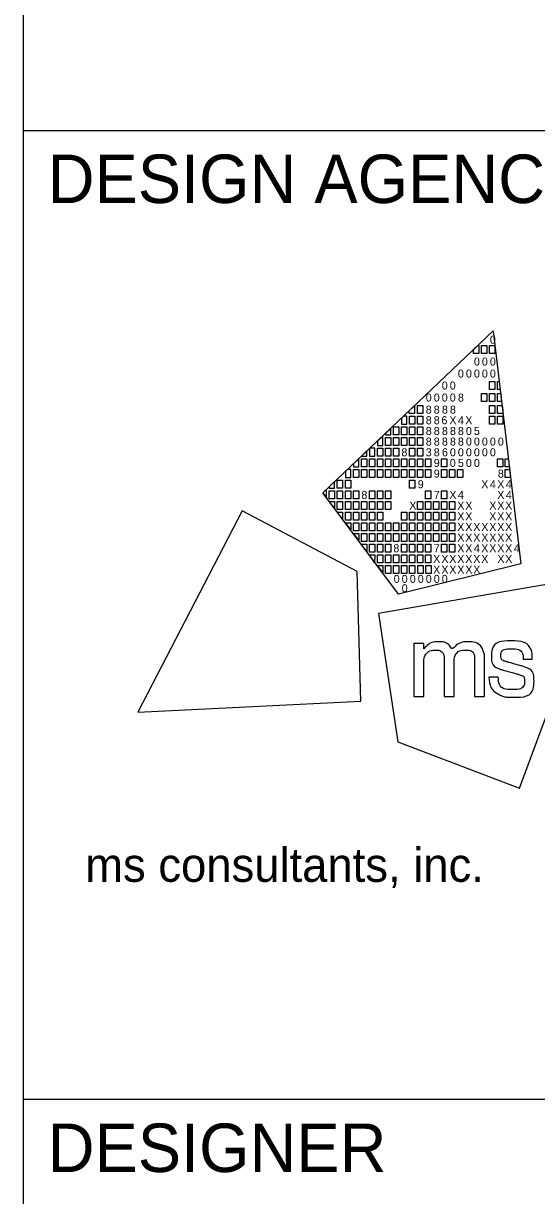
# Model space of a CAD drawing. Extents: x -0.1 to 34, y 0 to 22.
# Drawn here: x 32 to 33.058, y 2.301 to 4.721 of the extents above; entities that cross this region are included whole.
import ezdxf

# ---------------------------------------------------------------- set-up
doc = ezdxf.new("R2010")
doc.units = 0
doc.layers.add('SH_Border', color=7, linetype='Continuous')
doc.layers.add('SH_Data', color=7, linetype='Continuous')

msp = doc.modelspace()

# ---------------------------------------------------------------- linework, layer by layer
at = {"layer": 'SH_Border'}
for p, q in [((32, 0.5), (32, 21.5)), ((32, 4.5), (33.5, 4.5)), ((32, 2.5), (33.5, 2.5))]:
    msp.add_line(p, q, dxfattribs=at)
at = {"layer": 'SH_Data'}
for p, q in [((32.6175, 3.7519), (32.9688, 4.0861)), ((32.9688, 4.0861), (32.9688, 4.0861)), ((32.9688, 4.0861), (33.0253, 3.6052)), ((32.773, 3.543), (32.6175, 3.7519)), ((33.0253, 3.6052), (32.773, 3.543)), ((32.75, 3.5), (32.75, 3.5))]:
    msp.add_line(p, q, dxfattribs=at)
for points in [[(32.9279, 4.0472), (32.9369, 4.0558), (32.9389, 4.0558), (32.9389, 4.0393), (32.9279, 4.0393)], [(32.9444, 4.0558), (32.9554, 4.0558), (32.9554, 4.0393), (32.9444, 4.0393)], [(32.9609, 4.0558), (32.9719, 4.0558), (32.9719, 4.0393), (32.9609, 4.0393)], [(32.9606, 3.9815), (32.9716, 3.9815), (32.9716, 3.965), (32.9606, 3.965)], [(32.9771, 3.9815), (32.9811, 3.9815), (32.983, 3.965), (32.9771, 3.965)], [(32.9441, 3.9567), (32.9551, 3.9567), (32.9551, 3.9402), (32.9441, 3.9402)], [(32.9606, 3.9567), (32.9716, 3.9567), (32.9716, 3.9402), (32.9606, 3.9402)], [(32.9771, 3.9567), (32.984, 3.9567), (32.9859, 3.9402), (32.9771, 3.9402)], [(32.7953, 3.9211), (32.8064, 3.9316), (32.8064, 3.9154), (32.7953, 3.9154)], [(32.8123, 3.9319), (32.8233, 3.9319), (32.8233, 3.9154), (32.8123, 3.9154)], [(32.9606, 3.9319), (32.9716, 3.9319), (32.9716, 3.9154), (32.9606, 3.9154)], [(32.9771, 3.9319), (32.9869, 3.9319), (32.9881, 3.9218), (32.9881, 3.9154), (32.9771, 3.9154)], [(32.7958, 3.9099), (32.8068, 3.9099), (32.8068, 3.8934), (32.7958, 3.8934)], [(32.8123, 3.9099), (32.8233, 3.9099), (32.8233, 3.8934), (32.8123, 3.8934)], [(32.9606, 3.9099), (32.9716, 3.9099), (32.9716, 3.8934), (32.9606, 3.8934)], [(32.9771, 3.9099), (32.9881, 3.9099), (32.9881, 3.8934), (32.9771, 3.8934)], [(32.7627, 3.8879), (32.7737, 3.8879), (32.7737, 3.8714), (32.7627, 3.8714)], [(32.7793, 3.8879), (32.7903, 3.8879), (32.7903, 3.8714), (32.7793, 3.8714)], [(32.7958, 3.8879), (32.8068, 3.8879), (32.8068, 3.8714), (32.7958, 3.8714)], [(32.8123, 3.8879), (32.8233, 3.8879), (32.8233, 3.8714), (32.8123, 3.8714)], [(32.7462, 3.8659), (32.7572, 3.8659), (32.7572, 3.8494), (32.7462, 3.8494)], [(32.7627, 3.8659), (32.7737, 3.8659), (32.7737, 3.8494), (32.7627, 3.8494)], [(32.7793, 3.8659), (32.7903, 3.8659), (32.7903, 3.8494), (32.7793, 3.8494)], [(32.7958, 3.8659), (32.8068, 3.8659), (32.8068, 3.8494), (32.7958, 3.8494)], [(32.8123, 3.8659), (32.8233, 3.8659), (32.8233, 3.8494), (32.8123, 3.8494)], [(32.7297, 3.8439), (32.7407, 3.8439), (32.7407, 3.8273), (32.7297, 3.8273)], [(32.7462, 3.8439), (32.7572, 3.8439), (32.7572, 3.8273), (32.7462, 3.8273)], [(32.7627, 3.8439), (32.7737, 3.8439), (32.7737, 3.8273), (32.7627, 3.8273)], [(32.7958, 3.8439), (32.8068, 3.8439), (32.8068, 3.8273), (32.7958, 3.8273)], [(32.8123, 3.8439), (32.8233, 3.8439), (32.8233, 3.8273), (32.8123, 3.8273)], [(32.6802, 3.7998), (32.6912, 3.7998), (32.6912, 3.7833), (32.6802, 3.7833)], [(32.6967, 3.8218), (32.7077, 3.8218), (32.7077, 3.8053), (32.6967, 3.8053)], [(32.6967, 3.7998), (32.7077, 3.7998), (32.7077, 3.7833), (32.6967, 3.7833)], [(32.7132, 3.8218), (32.7242, 3.8218), (32.7242, 3.8053), (32.7132, 3.8053)], [(32.7132, 3.7998), (32.7242, 3.7998), (32.7242, 3.7833), (32.7132, 3.7833)], [(32.7297, 3.8218), (32.7407, 3.8218), (32.7407, 3.8053), (32.7297, 3.8053)], [(32.7297, 3.7998), (32.7407, 3.7998), (32.7407, 3.7833), (32.7297, 3.7833)], [(32.7462, 3.8218), (32.7572, 3.8218), (32.7572, 3.8053), (32.7462, 3.8053)], [(32.7462, 3.7998), (32.7572, 3.7998), (32.7572, 3.7833), (32.7462, 3.7833)], [(32.7627, 3.8218), (32.7737, 3.8218), (32.7737, 3.8053), (32.7627, 3.8053)], [(32.7627, 3.7998), (32.7737, 3.7998), (32.7737, 3.7833), (32.7627, 3.7833)], [(32.7793, 3.8218), (32.7903, 3.8218), (32.7903, 3.8053), (32.7793, 3.8053)], [(32.7793, 3.7998), (32.7903, 3.7998), (32.7903, 3.7833), (32.7793, 3.7833)], [(32.7958, 3.8218), (32.8068, 3.8218), (32.8068, 3.8053), (32.7958, 3.8053)], [(32.7958, 3.7998), (32.8068, 3.7998), (32.8068, 3.7833), (32.7958, 3.7833)], [(32.8123, 3.8218), (32.8233, 3.8218), (32.8233, 3.8053), (32.8123, 3.8053)], [(32.8123, 3.7998), (32.8233, 3.7998), (32.8233, 3.7833), (32.8123, 3.7833)], [(32.8288, 3.8218), (32.8398, 3.8218), (32.8398, 3.8053), (32.8288, 3.8053)], [(32.8288, 3.7998), (32.8398, 3.7998), (32.8398, 3.7833), (32.8288, 3.7833)], [(32.8618, 3.8218), (32.8728, 3.8218), (32.8728, 3.8053), (32.8618, 3.8053)], [(32.8618, 3.7998), (32.8728, 3.7998), (32.8728, 3.7833), (32.8618, 3.7833)], [(32.8783, 3.7998), (32.8893, 3.7998), (32.8893, 3.7833), (32.8783, 3.7833)], [(32.8947, 3.7998), (32.9057, 3.7998), (32.9057, 3.7833), (32.8947, 3.7833)], [(32.9771, 3.8218), (32.9881, 3.8218), (32.9881, 3.8053), (32.9771, 3.8053)], [(32.9935, 3.8218), (32.9998, 3.8218), (33.0018, 3.8053), (32.9935, 3.8053)], [(32.9935, 3.7998), (33.0024, 3.7998), (33.0044, 3.7833), (32.9935, 3.7833)], [(32.6471, 3.7778), (32.6581, 3.7778), (32.6581, 3.7613), (32.6471, 3.7613)], [(32.6637, 3.7778), (32.6747, 3.7778), (32.6747, 3.7613), (32.6637, 3.7613)], [(32.7958, 3.7778), (32.8068, 3.7778), (32.8068, 3.7613), (32.7958, 3.7613)], [(32.6306, 3.7558), (32.6416, 3.7558), (32.6416, 3.7393), (32.6306, 3.7393)], [(32.6471, 3.7558), (32.6581, 3.7558), (32.6581, 3.7393), (32.6471, 3.7393)], [(32.6637, 3.7558), (32.6747, 3.7558), (32.6747, 3.7393), (32.6637, 3.7393)], [(32.6802, 3.7558), (32.6912, 3.7558), (32.6912, 3.7393), (32.6802, 3.7393)], [(32.7132, 3.7558), (32.7242, 3.7558), (32.7242, 3.7393), (32.7132, 3.7393)], [(32.7297, 3.7558), (32.7407, 3.7558), (32.7407, 3.7393), (32.7297, 3.7393)], [(32.7462, 3.7558), (32.7572, 3.7558), (32.7572, 3.7393), (32.7462, 3.7393)], [(32.8288, 3.7558), (32.8398, 3.7558), (32.8398, 3.7393), (32.8288, 3.7393)], [(32.8618, 3.7558), (32.8728, 3.7558), (32.8728, 3.7393), (32.8618, 3.7393)], [(32.6306, 3.7338), (32.6416, 3.7338), (32.6416, 3.72)], [(32.6471, 3.7338), (32.6581, 3.7338), (32.6581, 3.7173), (32.6471, 3.7173)], [(32.6637, 3.7338), (32.6747, 3.7338), (32.6747, 3.7173), (32.6637, 3.7173)], [(32.6802, 3.7338), (32.6912, 3.7338), (32.6912, 3.7173), (32.6802, 3.7173)], [(32.6967, 3.7338), (32.7077, 3.7338), (32.7077, 3.7173), (32.6967, 3.7173)], [(32.7132, 3.7338), (32.7242, 3.7338), (32.7242, 3.7173), (32.7132, 3.7173)], [(32.7297, 3.7338), (32.7407, 3.7338), (32.7407, 3.7173), (32.7297, 3.7173)], [(32.7462, 3.7338), (32.7572, 3.7338), (32.7572, 3.7173), (32.7462, 3.7173)], [(32.8123, 3.7338), (32.8233, 3.7338), (32.8233, 3.7173), (32.8123, 3.7173)], [(32.8288, 3.7338), (32.8398, 3.7338), (32.8398, 3.7173), (32.8288, 3.7173)], [(32.8453, 3.7338), (32.8563, 3.7338), (32.8563, 3.7173), (32.8453, 3.7173)], [(32.8618, 3.7338), (32.8728, 3.7338), (32.8728, 3.7173), (32.8618, 3.7173)], [(32.8783, 3.7338), (32.8893, 3.7338), (32.8893, 3.7173), (32.8783, 3.7173)], [(32.6471, 3.7117), (32.6581, 3.7117), (32.6581, 3.698)], [(32.6637, 3.7117), (32.6747, 3.7117), (32.6747, 3.6952), (32.6637, 3.6952)], [(32.6802, 3.7117), (32.6912, 3.7117), (32.6912, 3.6952), (32.6802, 3.6952)], [(32.6967, 3.7117), (32.7077, 3.7117), (32.7077, 3.6952), (32.6967, 3.6952)], [(32.7132, 3.7117), (32.7242, 3.7117), (32.7242, 3.6952), (32.7132, 3.6952)], [(32.7297, 3.7117), (32.7407, 3.7117), (32.7407, 3.6952), (32.7297, 3.6952)], [(32.7793, 3.7117), (32.7903, 3.7117), (32.7903, 3.6952), (32.7793, 3.6952)], [(32.7958, 3.7117), (32.8068, 3.7117), (32.8068, 3.6952), (32.7958, 3.6952)], [(32.8123, 3.7117), (32.8233, 3.7117), (32.8233, 3.6952), (32.8123, 3.6952)], [(32.8288, 3.7117), (32.8398, 3.7117), (32.8398, 3.6952), (32.8288, 3.6952)], [(32.8453, 3.7117), (32.8563, 3.7117), (32.8563, 3.6952), (32.8453, 3.6952)], [(32.8618, 3.7117), (32.8728, 3.7117), (32.8728, 3.6952), (32.8618, 3.6952)], [(32.8783, 3.7117), (32.8893, 3.7117), (32.8893, 3.6952), (32.8783, 3.6952)], [(32.6637, 3.6897), (32.6747, 3.6897), (32.6747, 3.676)], [(32.6747, 3.6897), (32.6747, 3.6897), (32.6747, 3.6897)], [(32.6802, 3.6897), (32.6912, 3.6897), (32.6912, 3.6732), (32.6802, 3.6732)], [(32.6967, 3.6897), (32.7077, 3.6897), (32.7077, 3.6732), (32.6967, 3.6732)], [(32.7132, 3.6897), (32.7242, 3.6897), (32.7242, 3.6732), (32.7132, 3.6732)], [(32.7297, 3.6897), (32.7407, 3.6897), (32.7407, 3.6732), (32.7297, 3.6732)], [(32.7462, 3.6897), (32.7572, 3.6897), (32.7572, 3.6732), (32.7462, 3.6732)], [(32.7627, 3.6897), (32.7737, 3.6897), (32.7737, 3.6732), (32.7627, 3.6732)], [(32.7793, 3.6897), (32.7903, 3.6897), (32.7903, 3.6732), (32.7793, 3.6732)], [(32.7958, 3.6897), (32.8068, 3.6897), (32.8068, 3.6732), (32.7958, 3.6732)], [(32.8123, 3.6897), (32.8233, 3.6897), (32.8233, 3.6732), (32.8123, 3.6732)], [(32.8288, 3.6897), (32.8398, 3.6897), (32.8398, 3.6732), (32.8288, 3.6732)], [(32.8453, 3.6897), (32.8563, 3.6897), (32.8563, 3.6732), (32.8453, 3.6732)], [(32.8618, 3.6897), (32.8728, 3.6897), (32.8728, 3.6732), (32.8618, 3.6732)], [(32.8783, 3.6897), (32.8893, 3.6897), (32.8893, 3.6732), (32.8783, 3.6732)], [(32.6802, 3.6677), (32.6912, 3.6677), (32.6912, 3.654)], [(32.6967, 3.6677), (32.7077, 3.6677), (32.7077, 3.6512), (32.6967, 3.6512)], [(32.7132, 3.6677), (32.7242, 3.6677), (32.7242, 3.6512), (32.7132, 3.6512)], [(32.7297, 3.6677), (32.7407, 3.6677), (32.7407, 3.6512), (32.7297, 3.6512)], [(32.7462, 3.6677), (32.7572, 3.6677), (32.7572, 3.6512), (32.7462, 3.6512)], [(32.7627, 3.6677), (32.7737, 3.6677), (32.7737, 3.6512), (32.7627, 3.6512)], [(32.7793, 3.6677), (32.7903, 3.6677), (32.7903, 3.6512), (32.7793, 3.6512)], [(32.7958, 3.6677), (32.8068, 3.6677), (32.8068, 3.6512), (32.7958, 3.6512)], [(32.8123, 3.6677), (32.8233, 3.6677), (32.8233, 3.6512), (32.8123, 3.6512)], [(32.8288, 3.6677), (32.8398, 3.6677), (32.8398, 3.6512), (32.8288, 3.6512)], [(32.8453, 3.6677), (32.8563, 3.6677), (32.8563, 3.6512), (32.8453, 3.6512)], [(32.8618, 3.6677), (32.8728, 3.6677), (32.8728, 3.6512), (32.8618, 3.6512)], [(32.8783, 3.6677), (32.8893, 3.6677), (32.8893, 3.6512), (32.8783, 3.6512)], [(32.7077, 3.6305), (32.6965, 3.6457), (32.7077, 3.6457)], [(32.7132, 3.6457), (32.7242, 3.6457), (32.7242, 3.6292), (32.7132, 3.6292)], [(32.7297, 3.6457), (32.7407, 3.6457), (32.7407, 3.6292), (32.7297, 3.6292)], [(32.7462, 3.6457), (32.7572, 3.6457), (32.7572, 3.6292), (32.7462, 3.6292)], [(32.7793, 3.6457), (32.7903, 3.6457), (32.7903, 3.6292), (32.7793, 3.6292)], [(32.7958, 3.6457), (32.8068, 3.6457), (32.8068, 3.6292), (32.7958, 3.6292)], [(32.8123, 3.6457), (32.8233, 3.6457), (32.8233, 3.6292), (32.8123, 3.6292)], [(32.8288, 3.6457), (32.8398, 3.6457), (32.8398, 3.6292), (32.8288, 3.6292)], [(32.8618, 3.6457), (32.8728, 3.6457), (32.8728, 3.6292), (32.8618, 3.6292)], [(32.8783, 3.6457), (32.8893, 3.6457), (32.8893, 3.6292), (32.8783, 3.6292)], [(32.724, 3.6082), (32.7132, 3.6237), (32.7242, 3.6237)], [(32.7297, 3.6237), (32.7407, 3.6237), (32.7407, 3.6072), (32.7297, 3.6072)], [(32.7462, 3.6237), (32.7572, 3.6237), (32.7572, 3.6072), (32.7462, 3.6072)], [(32.7627, 3.6237), (32.7737, 3.6237), (32.7737, 3.6072), (32.7627, 3.6072)], [(32.7793, 3.6237), (32.7903, 3.6237), (32.7903, 3.6072), (32.7793, 3.6072)], [(32.7958, 3.6237), (32.8068, 3.6237), (32.8068, 3.6072), (32.7958, 3.6072)], [(32.8123, 3.6237), (32.8233, 3.6237), (32.8233, 3.6072), (32.8123, 3.6072)], [(32.8288, 3.6237), (32.8398, 3.6237), (32.8398, 3.6072), (32.8288, 3.6072)], [(32.7302, 3.6017), (32.7407, 3.6017), (32.7408, 3.5875)], [(32.7463, 3.6017), (32.7573, 3.6017), (32.7573, 3.5852), (32.7463, 3.5852)], [(32.763, 3.6017), (32.774, 3.6017), (32.774, 3.5852), (32.763, 3.5852)], [(32.7794, 3.6017), (32.7904, 3.6017), (32.7904, 3.5852), (32.7794, 3.5852)], [(32.796, 3.6017), (32.807, 3.6017), (32.807, 3.5852), (32.796, 3.5852)], [(32.8129, 3.6017), (32.8239, 3.6017), (32.8239, 3.5851), (32.8129, 3.5851)], [(32.8296, 3.6017), (32.8406, 3.6017), (32.8406, 3.5851), (32.8296, 3.5851)]]:
    msp.add_lwpolyline(points, close=True, dxfattribs=at)
for points in [[(32.7903, 3.9099), (32.7836, 3.9099), (32.7793, 3.9058), (32.7793, 3.8934), (32.7903, 3.8934), (32.7903, 3.9099)], [(32.7572, 3.8849), (32.7462, 3.8744), (32.7462, 3.8714), (32.7572, 3.8714), (32.7572, 3.8849)], [(32.7407, 3.8691), (32.7297, 3.8587), (32.7297, 3.8494), (32.7407, 3.8494), (32.7407, 3.8691)], [(32.7077, 3.8377), (32.6968, 3.8273), (32.7077, 3.8273), (32.7077, 3.8377)], [(32.7242, 3.8439), (32.7141, 3.8439), (32.7132, 3.843), (32.7132, 3.8273), (32.7242, 3.8273), (32.7242, 3.8439)], [(32.6747, 3.7998), (32.6679, 3.7998), (32.6637, 3.7958), (32.6637, 3.7833), (32.6747, 3.7833), (32.6747, 3.7998)], [(32.6912, 3.822), (32.6802, 3.8115), (32.6802, 3.8053), (32.6912, 3.8053), (32.6912, 3.822)], [(32.6416, 3.7749), (32.6306, 3.7644), (32.6306, 3.7613), (32.6416, 3.7613), (32.6416, 3.7749)], [(32.6251, 3.7558), (32.6216, 3.7558), (32.6175, 3.7519), (32.6251, 3.7417), (32.6251, 3.7558)], [(32.4512, 3.7149), (32.2359, 3.2988), (32.6956, 3.3215), (32.6884, 3.5892), (32.4512, 3.7149)], [(33.0229, 3.1422), (33.1859, 3.5814), (32.7324, 3.5029), (32.7722, 3.2381), (33.0229, 3.1422)]]:
    msp.add_lwpolyline(points, dxfattribs=at)
for points in [[(32.8048, 3.3315), (32.8048, 3.3315), (32.8048, 3.4409), (32.8048, 3.4409), (32.8048, 3.4409), (32.8255, 3.4409), (32.8255, 3.4409), (32.8255, 3.4409), (32.8255, 3.4297), (32.8255, 3.4297), (32.8346, 3.4399), (32.8457, 3.4445), (32.8555, 3.4445), (32.8688, 3.4445), (32.8791, 3.4372), (32.8837, 3.4266), (32.8915, 3.4381), (32.905, 3.4446), (32.9166, 3.4446), (32.9325, 3.4446), (32.9451, 3.435), (32.9494, 3.4213), (32.9494, 3.4212), (32.9494, 3.4212), (32.9494, 3.4212), (32.9501, 3.419), (32.9506, 3.4172), (32.9506, 3.4071), (32.9506, 3.4071), (32.9506, 3.3314), (32.9506, 3.3314), (32.9506, 3.3314), (32.9303, 3.3314), (32.9303, 3.3314), (32.9303, 3.3314), (32.9303, 3.4048), (32.9303, 3.4048), (32.9303, 3.4201), (32.9219, 3.4274), (32.911, 3.4274), (32.8995, 3.4274), (32.8879, 3.4171), (32.8879, 3.4001), (32.8879, 3.4001), (32.8879, 3.3315), (32.8879, 3.3315), (32.8879, 3.3315), (32.8674, 3.3315), (32.8674, 3.3315), (32.8674, 3.3315), (32.8674, 3.4059), (32.8674, 3.4059), (32.8674, 3.4203), (32.8588, 3.4274), (32.8496, 3.4274), (32.8384, 3.4274), (32.8254, 3.417), (32.8254, 3.3962), (32.8254, 3.3962), (32.8254, 3.3315), (32.8254, 3.3315), (32.8254, 3.3315), (32.8048, 3.3315), (32.8048, 3.3315)], [(32.9595, 3.3709), (32.9595, 3.3709), (32.9595, 3.3717), (32.9595, 3.3717), (32.9595, 3.3717), (32.9603, 3.3717), (32.9603, 3.3717), (32.9603, 3.3717), (32.9783, 3.3717), (32.9783, 3.3717), (32.9783, 3.3717), (32.9789, 3.3717), (32.9789, 3.3717), (32.9789, 3.3717), (32.979, 3.371), (32.979, 3.371), (32.9803, 3.3554), (32.9887, 3.346), (33.009, 3.346), (33.0273, 3.346), (33.0333, 3.3554), (33.0333, 3.3631), (33.0333, 3.3732), (33.0256, 3.3758), (33.0175, 3.378), (33.0175, 3.378), (32.987, 3.3867), (32.987, 3.3867), (32.972, 3.3909), (32.9648, 3.4019), (32.9648, 3.4142), (32.9648, 3.4303), (32.9768, 3.4462), (33.0052, 3.4462), (33.0348, 3.4462), (33.0489, 3.4285), (33.0489, 3.4095), (33.0489, 3.4095), (33.0489, 3.4087), (33.0489, 3.4087), (33.0489, 3.4087), (33.0482, 3.4087), (33.0482, 3.4087), (33.0482, 3.4087), (33.0312, 3.4087), (33.0312, 3.4087), (33.0312, 3.4087), (33.0305, 3.4087), (33.0305, 3.4087), (33.0305, 3.4087), (33.0305, 3.4094), (33.0305, 3.4094), (33.0301, 3.4208), (33.0226, 3.43), (33.0056, 3.43), (32.9891, 3.43), (32.9843, 3.4218), (32.9843, 3.4157), (32.9843, 3.4108), (32.9869, 3.4059), (32.9959, 3.4033), (32.9959, 3.4033), (33.0255, 3.3948), (33.0255, 3.3948), (33.0462, 3.3889), (33.0527, 3.3777), (33.0527, 3.3639), (33.0527, 3.3462), (33.041, 3.3298), (33.0087, 3.3298), (32.9952, 3.3298), (32.9877, 3.3321), (32.9823, 3.3348), (32.969, 3.3414), (32.9609, 3.3536), (32.9595, 3.3709)]]:
    msp.add_open_spline(points, degree=3, dxfattribs=at)

# ---------------------------------------------------------------- texts
for s, p in [('DESIGN AGENCY', (32.05, 4.35)), ('DESIGNER', (32.05, 2.35))]:
    msp.add_text(s, height=0.1, dxfattribs=at).set_placement(p)
for s, height, p in [('0', 0.0165, (32.9617, 4.0597)), ('0', 0.0165, (32.9288, 4.0145)), ('0', 0.0165, (32.9452, 4.0145)), ('0', 0.0165, (32.9617, 4.0145)), ('0', 0.0165, (32.8958, 3.9897)), ('0', 0.0165, (32.9123, 3.9897)), ('0', 0.0165, (32.9288, 3.9897)), ('0', 0.0165, (32.9452, 3.9897)), ('0', 0.0165, (32.9617, 3.9897)), ('0', 0.0165, (32.8625, 3.965)), ('0', 0.0165, (32.879, 3.965)), ('0', 0.0165, (32.8295, 3.9402)), ('0', 0.0165, (32.846, 3.9402)), ('0', 0.0165, (32.8625, 3.9402)), ('0', 0.0165, (32.879, 3.9402)), ('8', 0.0165, (32.8958, 3.9402)), ('8', 0.0165, (32.8295, 3.9154)), ('8', 0.0165, (32.846, 3.9154)), ('8', 0.0165, (32.8628, 3.9154)), ('8', 0.0165, (32.8793, 3.9154)), ('8', 0.0165, (32.8295, 3.8934)), ('8', 0.0165, (32.846, 3.8934)), ('6', 0.0165, (32.8618, 3.8934)), ('X', 0.0165, (32.8781, 3.8934)), ('4', 0.0165, (32.8958, 3.8934)), ('X', 0.0165, (32.911, 3.8934)), ('8', 0.0165, (32.8295, 3.8713)), ('8', 0.0165, (32.846, 3.8713)), ('8', 0.0165, (32.8628, 3.8713)), ('8', 0.0165, (32.8794, 3.8713)), ('8', 0.0165, (32.8958, 3.8713)), ('0', 0.0165, (32.9123, 3.8713)), ('5', 0.0165, (32.9287, 3.8713)), ('8', 0.0165, (32.8295, 3.8494)), ('8', 0.0165, (32.846, 3.8494)), ('8', 0.0165, (32.8628, 3.8494)), ('8', 0.0165, (32.8794, 3.8494)), ('8', 0.0165, (32.8958, 3.8494)), ('0', 0.0165, (32.9123, 3.8494)), ('0', 0.0165, (32.9288, 3.8494)), ('0', 0.0165, (32.9452, 3.8494)), ('0', 0.0165, (32.9617, 3.8494)), ('0', 0.0165, (32.9782, 3.8494)), ('8', 0.0165, (32.7793, 3.8273)), ('3', 0.0165, (32.8295, 3.8273)), ('8', 0.0165, (32.846, 3.8273)), ('6', 0.0165, (32.8629, 3.8273)), ('0', 0.0165, (32.8793, 3.8273)), ('0', 0.0165, (32.8958, 3.8273)), ('0', 0.0165, (32.9123, 3.8273)), ('0', 0.0165, (32.9288, 3.8273)), ('0', 0.0165, (32.9452, 3.8273)), ('0', 0.0165, (32.9617, 3.8273)), ('9', 0.0165, (32.846, 3.8053)), ('9', 0.0165, (32.846, 3.7833)), ('0', 0.0165, (32.879, 3.8053)), ('5', 0.0165, (32.8957, 3.8053)), ('0', 0.0165, (32.9123, 3.8053)), ('0', 0.0165, (32.9288, 3.8053)), ('8', 0.0165, (32.9781, 3.7833)), ('9', 0.0165, (32.813, 3.7613)), ('X', 0.0165, (32.9439, 3.7613)), ('4', 0.0165, (32.9617, 3.7613)), ('X', 0.0165, (32.9769, 3.7613)), ('4', 0.0165, (32.9946, 3.7613)), ('8', 0.0165, (32.6967, 3.7393)), ('7', 0.0165, (32.846, 3.7393)), ('X', 0.0165, (32.8781, 3.7393)), ('4', 0.0165, (32.8958, 3.7393)), ('X', 0.0165, (32.9769, 3.7393)), ('4', 0.0165, (32.9946, 3.7393)), ('X', 0.0165, (32.7955, 3.7173)), ('X', 0.0165, (32.8945, 3.7173)), ('X', 0.0165, (32.911, 3.7173)), ('X', 0.0165, (32.9604, 3.7173)), ('X', 0.0165, (32.9769, 3.7173)), ('X', 0.0165, (32.9933, 3.7173)), ('X', 0.0165, (32.8945, 3.6952)), ('X', 0.0165, (32.911, 3.6952)), ('X', 0.0165, (32.9604, 3.6952)), ('X', 0.0165, (32.9769, 3.6952)), ('X', 0.0165, (32.9933, 3.6952)), ('X', 0.0165, (32.8945, 3.6732)), ('X', 0.0165, (32.911, 3.6732)), ('X', 0.0165, (32.9274, 3.6732)), ('X', 0.0165, (32.9439, 3.6732)), ('X', 0.0165, (32.9604, 3.6732)), ('X', 0.0165, (32.9769, 3.6732)), ('X', 0.0165, (32.9933, 3.6732)), ('X', 0.0165, (32.8945, 3.6512)), ('X', 0.0165, (32.911, 3.6512)), ('X', 0.0165, (32.9274, 3.6512)), ('X', 0.0165, (32.9439, 3.6512)), ('X', 0.0165, (32.9604, 3.6512)), ('X', 0.0165, (32.9769, 3.6512)), ('X', 0.0165, (32.9933, 3.6512)), ('8', 0.0165, (32.7627, 3.6292)), ('7', 0.0165, (32.846, 3.6292)), ('X', 0.0165, (32.8945, 3.6292)), ('X', 0.0165, (32.911, 3.6292)), ('4', 0.0165, (32.9288, 3.6292)), ('X', 0.0165, (32.9439, 3.6292)), ('X', 0.0165, (32.9604, 3.6292)), ('X', 0.0165, (32.9769, 3.6292)), ('X', 0.0165, (32.9933, 3.6292)), ('4', 0.0165, (33.0111, 3.6292)), ('X', 0.0165, (32.8447, 3.6072)), ('X', 0.0165, (32.8616, 3.6072)), ('X', 0.0165, (32.878, 3.6072)), ('X', 0.0165, (32.8945, 3.6072)), ('X', 0.0165, (32.911, 3.6072)), ('X', 0.0165, (32.9274, 3.6072)), ('X', 0.0165, (32.9439, 3.6072)), ('X', 0.0165, (32.9771, 3.6072)), ('X', 0.0165, (32.9933, 3.6072)), ('0', 0.0165, (32.7634, 3.5659)), ('0', 0.0165, (32.7799, 3.5659)), ('0', 0.0165, (32.7965, 3.5659)), ('0', 0.0165, (32.813, 3.5659)), ('0', 0.0165, (32.8295, 3.5659)), ('X', 0.0165, (32.8447, 3.5851)), ('0', 0.0165, (32.846, 3.5659)), ('X', 0.0165, (32.8616, 3.5851)), ('0', 0.0165, (32.8625, 3.5659)), ('X', 0.0165, (32.878, 3.5851)), ('X', 0.0165, (32.8945, 3.5851)), ('X', 0.0165, (32.911, 3.5851)), ('X', 0.0165, (32.9274, 3.5851)), ('0', 0.0165, (32.7799, 3.5467)), ('ms consultants, inc.', 0.07, (32.1273, 2.9489))]:
    msp.add_text(s, height=height, rotation=360, dxfattribs=at).set_placement(p)

doc.saveas('drawing.dxf')
